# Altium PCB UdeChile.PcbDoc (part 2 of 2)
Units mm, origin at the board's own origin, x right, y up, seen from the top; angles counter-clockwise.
Board outline 201.93 x 30.26 mm, 2 copper layers (Top Layer, Bottom Layer); 212 components, 140 nets, 743 pads, 138 vias.
Unrouted connection lines stored in the file: 2.
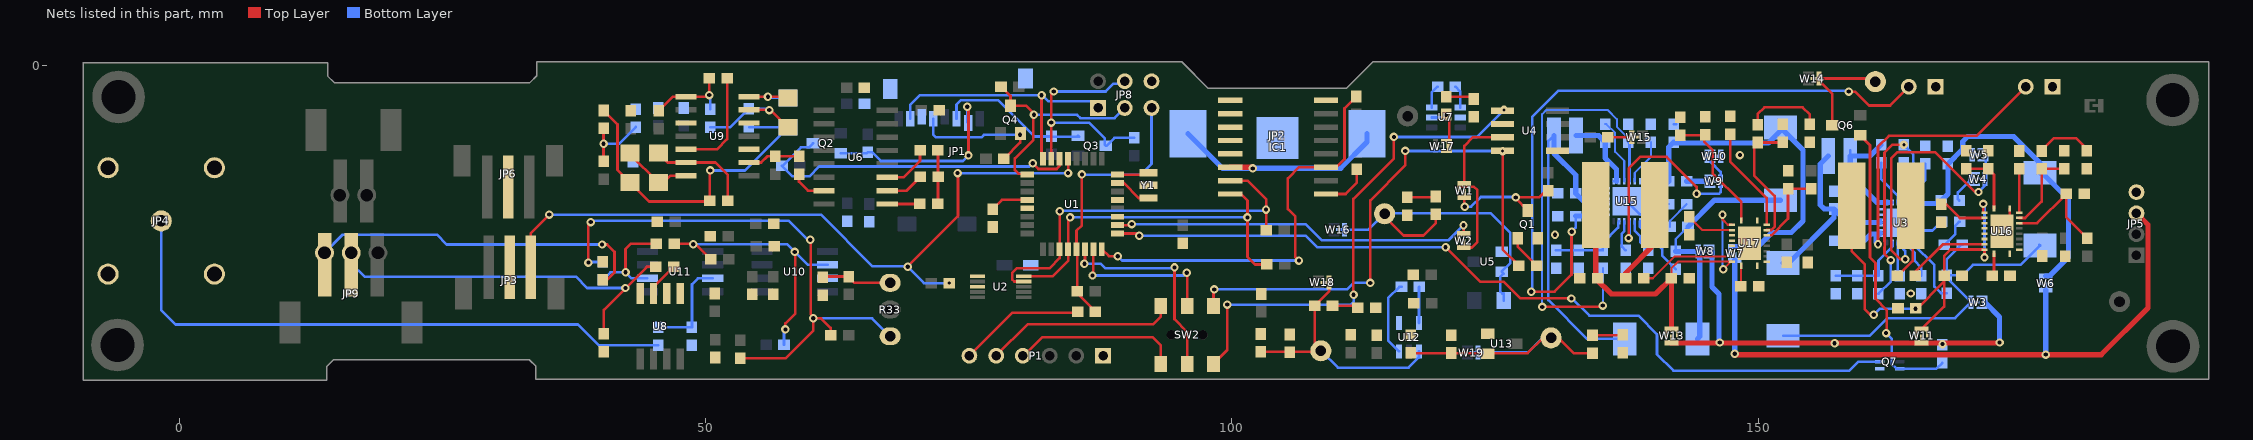
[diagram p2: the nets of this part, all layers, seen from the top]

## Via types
v1: diameter 0.8/0.8 (per signal layer), hole 0.4, Top Layer to Bottom Layer, tented both sides, 126 vias
v2: diameter 0.8/0.8 (per signal layer), hole 0.3, Top Layer to Bottom Layer, tented bottom, 6 vias
v3: diameter 0.8/0.8 (per signal layer), hole 0.3, Top Layer to Bottom Layer, tented top, 3 vias
v4: diameter 0.6/0.8 (per signal layer), hole 0.3, Top Layer to Bottom Layer, tented bottom, 2 vias
v5: diameter 0.8/0.8 (per signal layer), hole 0.4, Top Layer to Bottom Layer, tented bottom, 1 vias

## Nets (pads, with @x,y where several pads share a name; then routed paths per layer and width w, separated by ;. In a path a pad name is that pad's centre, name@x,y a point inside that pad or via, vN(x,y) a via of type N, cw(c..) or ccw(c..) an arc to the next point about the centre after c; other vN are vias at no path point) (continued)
CS: Q2.3 R71.1 U1.14 | length 32.1
  Top Layer w0.25: v1(81.073,-9.301) 81.606,-9.833 83.343,-9.833 83.633,-9.543 U1.14@83.633,-8.878
  Bottom Layer w0.25: Q2.3@60.204,-7.399 59.829,-7.774 59.063,-7.774 57.304,-9.534 R71.1@57.254,-9.534 58.249,-10.529 59.849,-10.529 60.776,-9.602 80.771,-9.602 v1(81.073,-9.301)
CS_L: JP1.2 Q2.2 R70.1 | length 19
  Top Layer w0.25: v1(74.855,-3.919) 74.967,-4.031 v1(74.967,-8.548)
  Bottom Layer w0.25: Q2.2@62.844,-8.349 65.292,-8.349 R70.1@65.402,-8.239 65.813,-8.239 66.649,-9.075 74.439,-9.075 v1(74.967,-8.548) ; v1(74.855,-3.919) 74.855,-5.397 JP1.2@74.929,-5.471
D: R12.2 SW2.4 U4.4 | length 51.4
  Top Layer w0.25: SW2.4@98.243,-22.855 98.243,-21.358 v1(98.325,-21.276) ; v1(113.142,-20.661) 113.142,-12.819 113.14,-12.818 116.458,-9.5 v1(116.458,-8.124) ; U4.4@125.712,-8.107 125.712,-17.484 R12.2@127.25,-19.022
  Bottom Layer w0.25: v1(98.325,-21.276) 110.919,-21.276 111.534,-20.661 v1(113.142,-20.661) ; v1(116.458,-8.124) v4@125.716,-8.124
  other v4: 125.716,-8.137
D0/RX: SW2.2 U1.30 | length 19.8
  Top Layer w0.25: v1@86.033,-18.793 U1.30@86.033,-17.463 ; v1(94.539,-19.186) 94.539,-24.112 95.743,-25.316 SW2.2@95.743,-28.355
  Bottom Layer w0.25: v1(85.981,-18.846) 87.547,-18.846 87.979,-19.277 94.449,-19.277 v1(94.539,-19.186)
D1/TX: SW2.5 U1.31 | length 14.8
  Top Layer w0.25: v1(86.753,-19.958) 86.833,-19.878 U1.31@86.833,-17.463 ; v1(95.697,-19.686) 95.743,-19.731 SW2.5@95.743,-22.855
  Bottom Layer w0.25: v1(86.753,-19.958) 95.425,-19.958 v1(95.697,-19.686)
ENA_S_M: Q6.1 Q7.3 R76.1 | length 28.4
  Top Layer w0.25: Q6.1@159.676,-6.65 160.61,-7.583 160.61,-18.247 161.133,-18.77 ; 161.135,-18.773 161.133,-18.77 ; v1@162.27,-25.627 162.193,-25.551 162.193,-23.214 161.133,-22.153 161.133,-18.77
  Bottom Layer w0.25: v1(162.147,-25.428) 162.67,-25.95 162.67,-28.349 163.13,-28.809 Q7.3@163.445,-28.809 166.924,-28.809 R76.1@167.485,-28.248
ENA_SENS: Q7.5 U1.1 | length 79.3
  Top Layer w0.25: U1.1@89.126,-15.971 90.977,-15.971 v1(91.192,-16.186) ; v1(120.297,-17.264) 123.599,-20.566 125.835,-20.566 127.389,-22.12 132.225,-22.12 v1(132.248,-22.143)
  Bottom Layer w0.25: v1(91.192,-16.186) 107.02,-16.186 108.099,-17.264 v1(120.297,-17.264) ; v1@132.26,-22.085 133.948,-23.772 138.602,-23.772 140.383,-25.553 140.383,-27.446 141.931,-28.994 158.655,-28.994 159.49,-28.159 Q7.5@161.545,-28.159
GND: C1.1 C2.1 C3.1 C6.2 C7.1 C8.1 C10.1 C11.1 C12.1 C13.1 C15.2 C16.2 C17.2 C18.2 C19.2 C22.2 C23.2 C24.2 C25.2 C26.2 C27.2 C28.1 C29.1 C30.1 C31.1 C32.1 C33.1 C34.1 C35.1 C36.2 C37.1 C38.1 C39.1 C40.1 C41.1 C43.2 C44.1 C45.1 C46.2 C48.1 C49.2 C50.2 C51.2 C52.2 C53.2 C54.2 C55.2 C56.2 C58.1 C59.2 C60.2 C61.2 C62.2 C63.2 C64.2 C65.2 D3.1 IC1.8 IC1.9 IC1.10 IC1.11 IC1.12 IC1.13 JP1.0 JP1.6 JP2.2 JP3.2 JP4.2 JP5.4 JP6.2 JP8.6 LED2.2 LED5.2 P1.1 P2.1 P3.1 Q1.2 Q7.4 R20.1 R23.1 R25.1 R34.1 R36.2 R37.1 R41.2 R45.2 R48.1 R49.1 R52.2 R53.2 R56.1 R57.1 R61.1 R62.1 R65.1 R67.1 U1.3 U1.5 U1.21 U2.1 U2.3 U3.6 U3.17 U3.18 U3.25 U4.5 U5.1 U7.5 U8.4 U9.3 U9.5 U9.10 U10.3 U12.4 U13.1 U15.6 U15.17 U15.18 U15.25 U16.11 U16.12 U16.20 U16.21 U17.11 U17.12 U17.20 U17.21 W5.1 W10.1 Y1.2 | length 7.8
  Top Layer w0.2: U16.21@173.145,-15.739 173.895,-14.989 U16.20@173.895,-13.589
  Top Layer w0.25: C65.2@149.898,-20.838 C65.2@150.048,-20.988
  Bottom Layer w0.2: C41.1@141.965,-5.587 C41.1@142.251,-5.587
  Bottom Layer w0.25: U15.25@137.52,-12.914 138.77,-14.164 U15.6@139.42,-14.164 ; U3.25@163.514,-14.926 164.764,-16.176 U3.6@165.414,-16.176
  other v1: 164.486,-21.668 130.69,-16.076 148.257,-8.52
I/O: JP3.1 R8.2 U1.13 | length 69.1
  Top Layer w0.25: JP3.1@33.381,-19.177 33.381,-15.943 v1(35.15,-14.174) ; v1(69.192,-19.131) 69.192,-19.099 73.977,-14.314 v1@73.977,-10.227 ; v1(84.433,-10.227) U1.13@84.433,-8.878
  Bottom Layer w0.25: v1(35.15,-14.174) 60.951,-14.174 65.857,-19.08 69.136,-19.08 69.187,-19.131 v1(69.192,-19.131) ; v1@69.228,-19.173 70.733,-20.677 v2(73.136,-20.677) ; v1(73.931,-10.227) v1(84.433,-10.227)
MISO: JP1.7 JP8.1 U1.16 | length 26.2
  Top Layer w0.25: v1(81.911,-2.824) 81.911,-8.756 U1.16@82.033,-8.878
  Bottom Layer w0.25: JP1.7@69.429,-5.071 69.429,-3.759 70.364,-2.824 81.975,-2.824 82.564,-3.414 86.655,-3.414 JP8.1@87.28,-4.039
MOSI: JP8.4 Q3.3 R73.1 U1.15 | length 25.8
  Top Layer w0.25: U1.15@82.833,-8.878 82.846,-8.865 v1@82.846,-2.703 ; v1@82.846,-5.435 v1@82.846,-2.703 ; v1(83.075,-2.473) v1@82.846,-2.703
  Bottom Layer w0.25: v1(82.832,-5.435) 86.441,-5.435 87.914,-6.908 87.914,-7.513 Q3.3@88.014,-7.613 88.114,-7.613 88.844,-6.884 R73.1@90.733,-6.884 ; v1(83.075,-2.473) 88.006,-2.474 88.742,-1.738 89.58,-1.738 JP8.4@89.82,-1.499
MOSI_L: JP1.3 Q3.2 R72.1 | length 14.7
  Bottom Layer w0.25: JP1.3@73.829,-5.071 73.829,-3.718 74.253,-3.294 77.791,-3.294 81.244,-6.747 R72.1@82.856,-6.747 82.87,-6.761 85.472,-6.761 Q3.2@85.374,-6.663
NetC1_2: C1.2 D7.2 L1.2 U3.15 U3.16 | length 19.1
  Bottom Layer w0.25: 161.614,-14.926 U3.16@161.614,-14.676
  Bottom Layer w0.5: D7.2@152.36,-18.769 152.896,-18.769 157.202,-14.463 C1.2@157.202,-13.636 ; L1.2@156.648,-8.601 155.886,-9.362 155.886,-13.246 156.276,-13.636 C1.2@157.202,-13.636 ; 161.614,-14.926 158.492,-14.926 C1.2@157.202,-13.636
NetC3_2: C3.2 U1.20 | length 3.6
  Top Layer w0.25: C3.2@77.261,-13.651 78.141,-12.771 U1.20@80.541,-12.771
NetC4_1: C4.1 U3.21 | length 4.5
  Bottom Layer w0.25: C4.1@161.671,-9.232 161.671,-10.795 163.264,-12.388 U3.21@163.264,-13.026
NetC4_2: C4.2 L1.1 U3.19 U3.20 | length 10.9
  Bottom Layer w0.25: L1.1@158.748,-8.601 L1.1@158.748,-8.057 ; 162.514,-13.026 U3.20@162.764,-13.026
  Bottom Layer w0.5: C4.2@161.671,-7.532 160.602,-8.601 L1.1@158.748,-8.601 158.748,-10.505 161.269,-13.026 U3.19@162.264,-13.026 162.514,-13.026
NetC5_1: C5.1 pad.1@114.501,-14.09 R13.2 U5.2 W16.1 | length 31.9
  Top Layer w0.25: pad.1@114.501,-14.09 114.501,-14.351 116.304,-16.154 118.178,-16.154 119.378,-14.954 R13.2@119.378,-14.155
  Bottom Layer w0.25: W16.1@110.399,-15.603 W16.1@110.699,-15.603 112.988,-15.603 pad.1@114.501,-14.09 pad.1@114.456,-14.045 ; C5.1@125.811,-22.344 125.811,-21.669 125.688,-21.669 125.483,-21.464 125.483,-20.109 125.811,-19.78 U5.2@125.63,-19.599 126.455,-18.774 126.455,-15.94 124.555,-14.04 122.382,-14.04 122.377,-14.045 pad.1@114.456,-14.045 ; pad.1@114.456,-14.045 114.453,-14.045 114.448,-14.04 114.453,-14.042 pad.1@114.456,-14.045
NetC9_1: C9.1 U6.9 | length 3.1
  Top Layer w0.25: U6.9@67.252,-13.16 C9.1@70.349,-13.16
NetC9_2: C9.2 R15.2 R19.2 | length 5.1
  Top Layer w0.25: C9.2@72.069,-13.14 R15.2@72.069,-8.058
NetC14_1: C14.1 U7.4 | length 2.2
  Bottom Layer w0.25: C14.1@121.233,-2.013 121.679,-2.46 U7.4@121.679,-3.993
NetC14_2: C14.2 U7.3 | length 2.2
  Bottom Layer w0.25: U7.3@118.979,-3.993 118.979,-2.566 C14.2@119.533,-2.013
NetC16_1: C16.1 R24.1 U11.3 | length 9.5
  Bottom Layer w0.25: R24.1@45.483,-24.885 C16.1@48.701,-24.885 48.701,-20.801 49.279,-20.222 U11.3@50.675,-20.222
NetC20_1: C20.1 U12.3 | length 7.2
  Bottom Layer w0.25: U12.3@115.876,-27.17 114.84,-26.134 114.84,-22.112 115.911,-21.04 C20.1@116.104,-21.04
NetC20_2: C20.2 U12.5 | length 3.4
  Bottom Layer w0.25: U12.5@117.776,-24.47 117.776,-21.069 C20.2@117.804,-21.04
NetC21_1: C21.1 R27.2 R33.1 R68.1 | length 54.5
  Top Layer w0.25: v1(38.863,-18.729) 38.863,-15.1 v1(39.082,-14.882) ; C21.1@53.295,-27.82 57.61,-27.82 60.227,-25.202 v1(60.227,-24.023) ; v1(59.944,-16.56) 59.97,-16.586 59.97,-23.595 60.227,-23.852 v1(60.227,-24.023) ; R68.1@61.882,-25.629 61.882,-24.95 60.955,-24.023 v1(60.227,-24.023)
  Bottom Layer w0.25: v1(38.863,-18.729) 38.922,-18.67 R27.2@40.228,-18.67 ; v1(39.082,-14.882) 39.218,-14.746 57.856,-14.746 59.67,-16.56 v1(59.944,-16.56) ; v1(60.227,-24.023) 65.809,-24.023 67.523,-25.738 R33.1@67.528,-25.733
NetC26_1: C26.1 R31.1 R32.2 | length 6.9
  Top Layer w0.25: R32.2@40.301,-9.111 R31.1@40.301,-5.98
  Bottom Layer w0.25: v1(40.302,-7.448) 41.772,-7.448 C26.1@43.366,-5.854
NetC30_2: C30.2 C31.2 LED4.2 pad.1@108.451,-27.11 U12.1 W18.1 | length 23.4
  Top Layer w0.25: C30.2@102.755,-27.217 108.344,-27.217 pad.1@108.451,-27.11 ; pad.1@107.852,-26.511 LED4.2@107.852,-22.838 109.228,-21.462 W18.1@109.228,-20.619 W18.1@108.928,-20.619
  Bottom Layer w0.25: pad.1@108.451,-27.11 110.052,-28.711 116.781,-28.711 117.776,-27.716 U12.1@117.776,-27.17
NetC34_2: C34.2 C35.2 pad.1@130.316,-25.882 R39.2 U13.2 W19.1 | length 26.3
  Top Layer w0.25: C35.2@116.973,-27.315 116.998,-27.34 128.079,-27.34 129.537,-25.882 pad.1@130.316,-25.882 131.002,-25.882 132.46,-27.34 R39.2@134.252,-27.34
  Bottom Layer w0.25: W19.1@123.085,-27.275 W19.1@123.385,-27.275 128.122,-27.275 129.515,-25.882 pad.1@130.316,-25.882
NetC37_2: C37.2 U3.23 | length 4.3
  Bottom Layer w0.25: U3.23@164.264,-13.026 164.264,-12.52 165.862,-10.922 C37.2@165.862,-9.359
NetC38_2: C38.2 P2.2 U3.13 U3.14 | length 29.8
  Top Layer w0.25: v1(161.379,-16.99) 161.379,-7.715 162.401,-6.693 170.743,-6.693 P2.2@175.413,-2.022
  Bottom Layer w0.5: C38.2@158.965,-16.637 160.096,-16.637 160.725,-16.008 161.532,-16.008 ; v1(161.379,-16.99) 161.183,-16.795 161.183,-16.356 161.532,-16.008 ; 161.614,-15.926 161.532,-16.008
NetC39_2: C39.2 D6.2 R9.1 U3.1 U3.24 W6.2 | length 29.8
  Bottom Layer w0.25: U3.24@164.764,-13.026 U3.24@164.769,-13.021
  Bottom Layer w0.5: 165.454,-13.113 R9.1@167.12,-13.113 ; R9.1@167.402,-12.831 168.021,-12.212 C39.2@168.021,-9.359 169.424,-7.956 169.424,-7.228 169.901,-6.751 174.262,-6.751 176.774,-9.264 D6.2@176.774,-10.201 176.959,-10.201 179.475,-12.716 179.475,-18.204 177.678,-20.001 W6.2@177.318,-20.001
NetC40_2: C40.2 D9.2 L2.2 U15.15 U15.16 | length 34.3
  Bottom Layer w0.25: L2.2@130.592,-6.656 130.064,-7.184 130.064,-22.289 133.753,-25.978 D9.2@137.331,-25.978
  Bottom Layer w0.5: L2.2@130.592,-6.656 130.592,-8.357 132.655,-10.42 C40.2@132.655,-12.152 133.419,-12.916 135.602,-12.916
NetC41_2: C41.2 D8.2 R50.1 U15.1 U15.24 W7.2 | length 34.2
  Bottom Layer w0.25: R50.1@141.423,-11.083 R50.1@141.423,-11.009
  Bottom Layer w0.5: 139.399,-11.083 R50.1@141.423,-11.083 ; R50.1@141.496,-11.009 141.496,-7.756 C41.2@141.965,-7.287 ; C41.2@141.965,-7.368 150.956,-7.368 152.116,-6.208 D8.2@152.116,-5.896 154.245,-8.025 154.245,-14.763 153.139,-15.869 151.312,-15.869 149.98,-17.201 W7.2@147.769,-17.201
NetC42_1: C42.1 U15.21 | length 6.3
  Bottom Layer w0.2: C42.1@135.453,-5.57 135.569,-5.57 136.398,-6.4 136.398,-8.197 137.27,-9.069 U15.21@137.27,-11.014
NetC42_2: C42.2 L2.1 U15.19 U15.20 | length 7.2
  Bottom Layer w0.2: U15.19@136.27,-11.014 U15.19@136.27,-10.991
  Bottom Layer w0.5: L2.1@132.692,-6.656 134.838,-6.656 C42.2@135.453,-7.27 135.453,-8.786 136.523,-9.857 136.523,-10.991
NetC44_2: C44.2 U15.23 | length 4.4
  Bottom Layer w0.2: U15.23@138.27,-11.014 138.27,-10.201 139.806,-8.665 C44.2@139.806,-7.287
NetC45_2: C45.2 P3.2 U15.13 U15.14 | length 68.1
  Top Layer w0.25: v1(128.43,-21.495) 130.642,-21.495 132.259,-19.878 132.259,-15.806 v1(132.273,-15.792) ; v1(158.6,-2.487) 159.207,-2.487 160.529,-3.809 162.522,-3.809 P3.2@164.309,-2.022
  Bottom Layer w0.25: v1(128.43,-21.495) 128.526,-21.399 128.526,-4.908 131.042,-2.392 158.506,-2.392 v1(158.6,-2.487) ; v1(132.273,-15.792) 132.655,-15.41 C45.2@132.655,-14.311
  Bottom Layer w0.5: C45.2@132.655,-14.311 135.174,-14.311 135.557,-13.927
NetC46_1: C46.1 C48.2 L3.1 U16.2 U16.9 W11.2 | length 38.4
  Top Layer w0.25: L3.1@158.876,-13.331 158.876,-17.639 160.132,-18.895 160.132,-23.167 160.656,-23.69 v1(160.963,-23.69) ; v1(164.929,-23.113) 164.929,-23.265 167.653,-20.541 ; W11.2@165.513,-25.044 167.656,-22.901 167.653,-22.901 167.653,-20.541 ; v1(171.367,-13.151) 171.367,-13.86 U16.2@171.495,-13.989 ; v1@171.495,-18.235 U16.9@171.495,-17.489 168.245,-17.489 167.653,-18.081 C48.2@167.653,-19.963 167.653,-20.541
  Bottom Layer w0.25: v1(160.963,-23.69) 161.554,-23.099 164.764,-23.099 164.929,-23.265 v1(164.929,-23.113) ; v1(171.494,-18.235) v1@171.494,-13.279
NetC47_1: C47.1 L3.2 R58.2 U16.4 U16.5 U16.6 U16.7 | length 9.3
  Top Layer w0.25: C47.1@163.197,-19.96 163.296,-19.96 164.668,-18.588 164.668,-13.522 L3.2@164.476,-13.331 L3.2@163.332,-14.475 ; L3.2@165.312,-14.864 L3.2@165.474,-15.026 ; R58.2@167.348,-15.026 R58.2@167.385,-14.989
NetC47_2: C47.2 U16.8 | length 8
  Top Layer w0.25: C47.2@164.897,-19.96 164.897,-19.619 167.527,-16.989 U16.8@171.495,-16.989
NetC49_1: C49.1 C50.1 U16.1 | length 6.1
  Top Layer w0.25: C49.1@169.747,-9.809 C50.1@171.841,-9.809 172.395,-10.364 U16.1@172.395,-13.589
NetC51_1: C51.1 R60.2 U16.18 | length 8
  Top Layer w0.25: U16.18@174.795,-14.489 175.364,-14.489 176.916,-12.936 176.916,-9.809 C51.1@179.064,-9.809
NetC54_1: C54.1 R60.1 | length 5.4
  Top Layer w0.25: R60.1@176.911,-8.105 178.106,-6.91 180.203,-6.91 181.219,-7.926 C54.1@181.219,-8.066
NetC55_1: C55.1 U16.10 | length 2.1
  Top Layer w0.25: C55.1@172.395,-20.015 U16.10@172.395,-17.889
NetC56_1: C56.1 C58.2 L4.1 U17.2 U17.9 W13.2 | length 35.4
  Top Layer w0.2: L4.1@134.554,-13.256 L4.1@134.734,-13.436 ; C58.2@141.749,-19.92 141.749,-19.27 142.38,-18.639 U17.9@147.393,-18.639 ; v1(146.605,-14.194) 146.605,-14.64 147.103,-15.139 U17.2@147.498,-15.139 ; v1(146.668,-19.363) U17.9@147.393,-18.639 ; U17.9@147.498,-18.639 U17.9@147.393,-18.639
  Top Layer w0.5: L4.1@134.734,-13.436 134.554,-13.616 134.554,-20.237 136.04,-21.724 140.246,-21.724 C58.2@141.749,-20.221 141.749,-19.92 141.764,-19.935 W13.2@141.764,-25.039
  Bottom Layer w0.2: v1(146.605,-14.194) 146.605,-19.299 v1(146.668,-19.363)
NetC57_1: C57.1 L4.2 R63.2 U17.4 U17.5 U17.6 U17.7 | length 8.1
  Top Layer w0.2: L4.2@140.154,-16.969 L4.2@140.154,-13.256
  Top Layer w0.5: C57.1@137.409,-20.218 137.409,-19.714 L4.2@140.154,-16.969
NetC57_2: C57.2 U17.8 | length 9.2
  Top Layer w0.2: C57.2@139.109,-20.218 139.991,-20.218 142.07,-18.139 U17.8@147.498,-18.139
NetC59_1: C59.1 C60.1 U17.1 | length 11.9
  Top Layer w0.25: C59.1@142.586,-6.638 144.878,-6.638 144.878,-7.267 145.666,-8.055 145.666,-10.254 148.398,-12.987 U17.1@148.398,-14.739
NetC61_1: C61.1 R64.2 U17.18 | length 12.2
  Top Layer w0.25: U17.18@150.798,-15.639 151.246,-15.639 151.554,-15.331 151.554,-12.385 149.606,-10.437 149.606,-7.658 R64.2@149.941,-7.323 152.318,-7.323 C61.1@152.334,-7.307
NetC64_1: C64.1 R64.1 | length 7.4
  Top Layer w0.25: R64.1@149.941,-5.623 149.941,-4.632 150.592,-3.981 154.221,-3.981 154.903,-4.663 C64.1@154.903,-5.606
NetC65_1: C65.1 U17.10 | length 2
  Top Layer w0.2: C65.1@148.348,-20.988 148.348,-19.089 U17.10@148.398,-19.039
NetD1_1: D1.1 R22.2 R30.1 U9.6 | length 10.8
  Top Layer w0.25: U9.6@54.118,-4.217 56.162,-4.217 D1.1@57.824,-5.879
  Bottom Layer w0.25: R30.1@50.432,-5.871 52.341,-5.871 R22.2@54.09,-4.122 55.919,-4.122 v1(56.042,-4.245)
NetD1_2: D1.2 D2.1 U9.7 | length 5.6
  Top Layer w0.25: U9.7@54.118,-2.967 v1(55.915,-2.967) D1.2@57.712,-2.967
  Bottom Layer w0.25: v1(55.915,-2.967) 56.027,-3.079 D2.1@57.824,-3.079
NetD2_2: D2.2 D5.2 R22.1 R31.2 R35.1 | length 31.9
  Top Layer w0.25: R31.2@40.301,-4.28 41.62,-5.6 41.62,-9.927 D5.2@42.824,-11.131 44.624,-12.931 50.305,-12.931 R35.1@50.395,-12.841 50.395,-10.022 v1(50.439,-9.977)
  Bottom Layer w0.25: v1(50.439,-9.977) 53.726,-9.977 D2.2@57.824,-5.879 R22.1@54.147,-5.879
NetD4_1: D4.1 R35.2 U9.13 | length 9.9
  Top Layer w0.25: D4.1@45.512,-8.331 46.398,-9.217 U9.13@48.118,-9.217 50.932,-9.217 52.095,-10.38 R35.2@52.095,-12.841
NetD4_2: D4.2 D5.1 U9.14 | length 6.8
  Top Layer w0.25: D5.1@42.824,-8.331 42.824,-8.442 D4.2@45.512,-11.131 45.993,-11.131 46.657,-10.467 U9.14@48.118,-10.467
NetIC1_1: IC1.1 R2.2 | length 4.6
  Top Layer w0.25: IC1.1@108.946,-12.21 110.797,-12.21 111.853,-11.153 R2.2@111.853,-9.877
NetIC1_14: IC1.14 JP2.1 | length 22.4
  Top Layer w0.5: IC1.14@99.846,-9.67 101.859,-9.67 v1(101.973,-9.784)
  Bottom Layer w0.5: JP2.1@95.823,-6.485 99.102,-9.765 110.33,-9.765 112.823,-7.272 JP2.1@112.823,-6.485
NetLED1_2: LED1.2 R46.1 | length 2.8
  Bottom Layer w0.25: LED1.2@167.679,-17.018 167.729,-17.018 168.7,-16.047 168.7,-15.234 169.075,-14.859 R46.1@169.125,-14.859
NetLED2_1: LED2.1 R13.1 | length 2.6
  Top Layer w0.25: LED2.1@116.674,-12.515 R13.1@119.318,-12.515
NetLED3_1: LED3.1 R20.2 | length 2.7
  Top Layer w0.25: LED3.1@120.365,-2.965 122.737,-2.965 R20.2@122.962,-3.19
NetLED3_2: LED3.2 U7.2 W17.2 | length 4.6
  Top Layer w0.25: LED3.2@120.365,-4.688 LED3.2@120.356,-4.697 ; W17.2@120.646,-7.658 120.646,-4.987 LED3.2@120.356,-4.697 ; LED3.2@120.356,-4.697 120.344,-4.685 v5(120.344,-4.709) LED3.2@120.356,-4.697
  Bottom Layer w0.25: U7.2@118.979,-4.943 120.11,-4.943 v5(120.344,-4.709)
NetLED4_1: LED4.1 R37.2 | length 2.2
  Top Layer w0.25: LED4.1@109.552,-22.838 R37.2@111.793,-22.838
NetLED5_1: LED5.1 R39.1 | length 2.8
  Top Layer w0.25: R39.1@134.252,-25.64 LED5.1@137.1,-25.64
NetLED6_2: LED6.2 R54.1 | length 2.8
  Bottom Layer w0.2: LED6.2@141.623,-15.327 141.623,-14.741 R54.1@143.196,-13.168
NetQ1_1: Q1.1 R12.1 | length 3.3
  Top Layer w0.25: Q1.1@127.15,-16.425 127.15,-17.222 R12.1@128.95,-19.022
NetQ1_3: Q1.3 R11.1 W1.1 | length 11.6
  Top Layer w0.25: W1.1@122.082,-12.236 W1.1@122.082,-12.536 122.082,-13.384 v1(122.118,-13.42) ; Q1.3@128.1,-13.785 126.963,-12.648 v1(126.963,-12.537) 129.192,-12.537 R11.1@130.084,-11.645
  Bottom Layer w0.25: v1(122.118,-13.42) 122.729,-13.42 123.646,-12.502 126.928,-12.502 v1(126.963,-12.537)
NetQ6_3: pad.1@161.131,-1.538 Q6.3 W14.1 | length 10.8
  Top Layer w0.25: W14.1@155.481,-1.244 W14.1@155.564,-1.244 ; Q6.3@157.036,-5.7 157.036,-2.717 W14.1@155.564,-1.244 ; pad.1@161.131,-1.538 160.837,-1.244 W14.1@155.781,-1.244 W14.1@155.564,-1.244
NetR9_2: R9.2 W4.2 | length 2.8
  Bottom Layer w0.25: R9.2@169.102,-12.831 168.966,-12.695 168.966,-12.071 W4.2@170.242,-10.795 170.242,-10.797 W4.2@170.117,-10.922
NetR10_1: R10.1 W15.1 | length 2.6
  Top Layer w0.25: R10.1@135.721,-6.812 W15.1@137.974,-6.812 W15.1@138.274,-6.812
NetR14_2: R14.2 R18.1 U9.2 | length 5
  Top Layer w0.25: U9.2@54.118,-9.217 55.265,-9.217 55.855,-8.628 R14.2@56.608,-8.628 56.622,-8.642 R18.1@58.873,-8.642
NetR15_1: R15.1 U6.11 | length 4.8
  Top Layer w0.25: U6.11@67.252,-10.62 68.824,-10.62 70.369,-9.076 R15.1@70.369,-8.058
NetR16_1: R16.1 R26.2 R28.2 U10.2 | length 26.9
  Top Layer w0.25: R26.2@47.002,-16.926 v1@48.818,-16.926 ; v1(48.818,-16.997) 49.07,-16.997 R28.2@50.483,-18.409 ; v1(57.579,-25.078) 57.579,-24.515 58.514,-23.58 58.514,-17.755 v1(58.472,-17.713)
  Bottom Layer w0.25: v1(48.818,-16.997) 57.756,-16.997 v1(58.472,-17.713) ; R16.1@57.441,-26.524 57.441,-25.216 v1(57.579,-25.078) ; v1@58.483,-17.702 59.733,-18.952 U10.2@61.577,-18.952
NetR17_2: R17.2 U8.1 U8.2
NetR18_2: R18.2 U6.7 | length 3.4
  Top Layer w0.25: R18.2@58.873,-10.342 58.873,-11.035 59.728,-11.89 U6.7@61.252,-11.89
NetR19_1: R19.1 U6.10 | length 3.7
  Top Layer w0.25: U6.10@67.252,-11.89 69.105,-11.89 70.388,-10.608 R19.1@70.388,-10.562
NetR21_1: R21.1 U8.3 | length 3.3
  Top Layer w0.25: U8.3@45.051,-21.655 45.051,-21.039 R21.1@46.959,-19.131
NetR26_1: R26.1 R27.1 U11.6 | length 10.1
  Top Layer w0.25: v1(42.391,-19.656) 42.391,-17.462 42.927,-16.926 R26.1@45.302,-16.926
  Bottom Layer w0.25: R27.1@40.228,-20.37 40.941,-19.656 v1(42.391,-19.656) 42.956,-20.222 U11.6@44.456,-20.222
NetR29_1: R29.1 R30.2 R38.2 U9.8 | length 8.4
  Top Layer w0.25: R29.1@45.547,-4.296 46.876,-2.967 U9.8@48.118,-2.967 50.199,-2.967 v1(50.352,-2.814) R38.2@50.352,-1.22
  Bottom Layer w0.25: v1(50.352,-2.814) 50.432,-2.894 R30.2@50.432,-4.171
NetR33_3: R33.3 R34.2 R69.2 | length 6.7
  Top Layer w0.25: R34.2@61.135,-20.135 61.213,-20.057 R69.2@63.591,-20.057 63.591,-20.107 64.137,-20.653 R33.3@67.528,-20.653
NetR38_1: R38.1 U9.12 | length 10.1
  Top Layer w0.25: U9.12@48.118,-7.967 51.091,-7.967 52.052,-7.006 R38.1@52.052,-1.22
NetR40_2: R40.2 U3.7 | length 6.4
  Bottom Layer w0.25: U3.7@164.764,-16.826 164.764,-16.996 166.726,-18.958 166.726,-21.018 167.347,-21.639 R40.2@167.894,-21.639
NetR41_1: R41.1 U3.10 | length 3.2
  Bottom Layer w0.25: U3.10@163.264,-16.826 163.264,-19.793 R41.1@163.449,-19.978
NetR45_1: R45.1 U3.8 | length 3.7
  Bottom Layer w0.25: U3.8@164.264,-16.826 164.264,-17.198 164.846,-17.78 164.846,-18.542 165.481,-19.177 R45.1@165.481,-19.978
NetR46_2: R46.2 U3.5 | length 2.3
  Bottom Layer w0.25: U3.5@165.414,-15.676 166.558,-15.676 167.375,-14.859 R46.2@167.425,-14.859
NetR47_1: R47.1 R48.2 R49.2 U3.11 | length 7.8
  Bottom Layer w0.25: R49.2@157.353,-19.978 R48.2@159.385,-19.978 R47.1@161.417,-19.978 161.417,-18.542 162.764,-17.195 U3.11@162.764,-16.826
NetR50_2: R50.2 W9.2 | length 1.9
  Bottom Layer w0.5: R50.2@143.196,-11.009 W9.2@145.116,-11.009
NetR51_2: R51.2 U15.7 | length 5.9
  Bottom Layer w0.25: U15.7@138.77,-14.814 138.77,-15.333 140.876,-17.439 140.876,-18.07 R51.2@142.159,-19.353
NetR52_1: R52.1 U15.10 | length 3
  Bottom Layer w0.25: U15.10@137.27,-14.814 137.27,-15.74 137.035,-15.976 137.035,-17.208 R52.1@137.393,-17.567
NetR53_1: R53.1 U15.8 | length 3.3
  Bottom Layer w0.25: U15.8@138.27,-14.814 138.27,-15.711 138.777,-16.217 138.777,-16.791 R53.1@139.552,-17.567
NetR54_2: R54.2 U15.5 | length 2.3
  Bottom Layer w0.2: U15.5@139.42,-13.664 140.276,-13.664 140.772,-13.168 R54.2@141.496,-13.168
NetR55_1: R55.1 R56.2 R57.2 U15.11 | length 7.8
  Bottom Layer w0.25: R57.2@130.789,-17.569 R56.2@132.955,-17.569 135.232,-17.569 R55.1@135.234,-17.567 135.234,-16.852 136.685,-15.402 136.685,-14.9 U15.11@136.77,-14.814
NetR58_1: R58.1 U16.3 | length 4.7
  Top Layer w0.25: R58.1@167.376,-13.2 167.87,-13.2 169.159,-14.489 U16.3@171.495,-14.489
NetR59_1: R59.1 R62.2 U16.17 | length 10.7
  Top Layer w0.25: U16.17@174.795,-14.989 176.496,-14.989 R62.2@179.276,-12.208 179.276,-14.427 R59.1@181.272,-16.422
NetR61_2: R61.2 U16.19 | length 4.2
  Top Layer w0.25: U16.19@174.795,-13.989 R61.2@174.795,-9.813
NetR63_1: R63.1 U17.3 | length 4.6
  Top Layer w0.2: R63.1@143.442,-14.395 144.685,-15.639 U17.3@147.498,-15.639
NetR65_2: R65.2 U17.19 | length 10
  Top Layer w0.25: R65.2@147.356,-6.522 147.356,-9.154 150.798,-12.596 U17.19@150.798,-15.139
NetR66_1: R66.1 R67.2 U17.17 | length 7.7
  Top Layer w0.25: U17.17@150.798,-16.139 151.241,-16.139 152.83,-14.55 R67.2@152.83,-11.723 R66.1@155.022,-11.723
NetU1_7: U1.7 Y1.3 | length 3.5
  Top Layer w0.25: U1.7@89.126,-11.17 89.723,-11.17 91.141,-12.588 Y1.3@92.067,-12.588
NetU1_8: U1.8 Y1.1 | length 3
  Top Layer w0.25: U1.8@89.126,-10.371 91.884,-10.371 Y1.1@92.067,-10.188
NetU3_9: U3.9 W4.1 W5.2 | length 26
  Top Layer w0.25: v1(163.957,-18.415) 163.505,-18.415 162.624,-17.534 162.624,-8.821 163.191,-8.254 166.823,-8.254 170.596,-12.026 v1(170.927,-12.026)
  Bottom Layer w0.25: U3.9@163.764,-16.826 163.764,-17.438 163.957,-17.631 v1(163.957,-18.415) ; v1(170.927,-12.026) 171.542,-11.411 W4.1@171.542,-10.795 171.592,-10.795 171.617,-10.77 171.617,-8.498 W5.2@171.623,-8.492
NetU15_9: U15.9 W9.1 W10.2 | length 22.6
  Top Layer w0.25: v1(137.686,-16.4) 137.686,-9.775 138.782,-8.679 141.295,-8.679 144.145,-11.529 v1(144.145,-12.192)
  Bottom Layer w0.25: v1(137.686,-16.4) 137.77,-16.315 U15.9@137.77,-14.814 ; v1(144.145,-12.192) 146.262,-12.192 146.42,-12.033 W9.1@146.42,-11.005 146.42,-10.124 W10.2@145.446,-9.15
PD2: IC1.3 R6.2 U1.32 | length 40
  Top Layer w0.25: U1.32@87.633,-17.463 88.296,-18.126 v1(89.146,-18.126) ; v1(106.365,-18.543) 106.021,-18.199 106.021,-14.347 105.313,-13.639 105.313,-10.74 106.383,-9.67 IC1.3@108.946,-9.67 109.923,-9.67 110.694,-8.899 110.694,-4.085 R6.2@111.825,-2.954
  Bottom Layer w0.25: v1(89.146,-18.126) 89.554,-18.534 106.355,-18.534 v1(106.365,-18.543)
PD4: U1.2 W2.2 | length 35
  Top Layer w0.25: U1.2@89.126,-15.17 90.379,-15.17 v1(90.475,-15.074) ; v1(121.994,-15.178) 122.022,-15.205 W2.2@122.022,-15.999
  Bottom Layer w0.25: v1(90.475,-15.074) 107,-15.074 108.55,-16.624 120.548,-16.624 v1(121.994,-15.178)
PH_IN: JP4.1 R24.2 | length 57.1
  Bottom Layer w0.25: JP4.1@-1.718,-14.772 -1.718,-23.259 -0.366,-24.61 37.871,-24.61 39.846,-26.585 R24.2@45.483,-26.585
R: SW2.3 U4.1 | length 47.1
  Top Layer w0.25: SW2.3@98.243,-28.355 99.554,-27.044 v1(99.554,-22.721) ; v1(111.56,-21.786) 111.54,-21.765 111.54,-12.668 115.388,-8.82 v1(115.388,-6.795)
  Bottom Layer w0.25: v1(99.554,-22.721) 111.299,-22.721 111.568,-22.452 111.56,-22.443 v1(111.56,-21.786) ; v1(115.388,-6.795) 123.271,-6.795 v4(125.845,-4.221)
RST: C66.1 JP8.5 R1.1 U1.29 | length 26.4
  Top Layer w0.25: v1(85.746,-10.358) 85.746,-15.188 85.233,-15.701 U1.29@85.233,-17.463 85.306,-17.536 R1.1@85.306,-21.448 85.306,-21.663 C66.1@87.031,-23.388
  Bottom Layer w0.25: v1@85.714,-10.374 91.348,-10.374 92.36,-9.363 JP8.5@92.36,-4.039
RST_: C66.2 P1.6 | length 12
  Top Layer w0.25: P1.6@75.058,-27.577 79.155,-23.48 85.239,-23.48 C66.2@85.331,-23.388
RX_FTDI: P1.5 SW2.6 | length 18.2
  Top Layer w0.25: P1.5@77.598,-27.577 80.602,-24.573 92.535,-24.573 93.243,-23.866 SW2.6@93.243,-22.855
SCK: JP8.3 Q4.3 R75.1 U1.17 | length 21.3
  Top Layer w0.25: R75.1@78.059,-2.028 78.109,-2.028 78.962,-2.881 Q4.3@78.962,-3.827 80.449,-3.827 81.136,-4.514 81.136,-7.071 79.367,-8.84 79.367,-9.942 79.703,-10.279 80.449,-10.279 U1.17@80.541,-10.371
  Bottom Layer w0.25: v1(81.187,-4.692) 85.273,-4.692 85.595,-5.014 88.845,-5.014 JP8.3@89.82,-4.039
SCK_L: JP1.5 Q4.2 R74.1 | length 12.8
  Top Layer w0.25: R74.1@78.382,-8.847 78.374,-8.84 79.875,-7.34 v1(79.875,-6.593)
  Bottom Layer w0.25: JP1.5@71.629,-5.071 71.629,-6.599 71.862,-6.832 76.21,-6.832 76.448,-6.593 v1(79.875,-6.593)
SCL: IC1.16 R5.1 U1.28 U2.10 | length 35.2
  Top Layer w0.25: U2.10@80.226,-20.032 82.964,-20.032 84.433,-18.562 U1.28@84.433,-17.463 84.433,-14.622 v1(84.619,-14.437) ; IC1.16@99.846,-12.21 100.858,-12.21 101.48,-12.832 101.48,-18.199 102.187,-18.906 R5.1@103.303,-18.906
  Bottom Layer w0.25: v1(84.619,-14.437) v1(101.47,-14.437)
SDA: IC1.15 R4.1 U1.27 U2.9 | length 38.1
  Top Layer w0.25: U2.9@80.226,-20.532 79.319,-20.532 79.118,-20.331 79.118,-19.703 79.565,-19.256 82.695,-19.256 83.633,-18.317 U1.27@83.633,-17.463 v1(83.633,-13.844) ; IC1.15@99.846,-10.94 101.483,-10.94 103.252,-12.709 R4.1@103.252,-15.652
  Bottom Layer w0.25: v1(83.633,-13.844) 83.666,-13.812 103.116,-13.812 v1(103.234,-13.694)
T_GND: JP9.3 pad.3@13.79,-17.804 R25.2 | length 32.3
  Top Layer w0.25: v1(40.166,-17.012) 40.649,-17.012 41.339,-17.702 41.339,-19.667 40.641,-20.365 R25.2@40.205,-20.365
  Bottom Layer w0.25: pad.3@13.79,-17.804 15.524,-16.069 24.457,-16.069 25.4,-17.012 v1(40.166,-17.012)
T_S: JP9.2 pad.2@16.33,-17.804 R21.2 R23.2 | length 36.9
  Top Layer w0.25: R23.2@40.333,-25.471 40.333,-23.214 44.417,-19.131 R21.2@45.26,-19.131
  Bottom Layer w0.25: pad.2@16.33,-17.804 16.33,-18.8 17.6,-20.07 37.667,-20.07 38.742,-21.145 v1(42.376,-21.145)
TX_EN: U4.2 U4.3 W1.2 W2.1 | length 16.2
  Top Layer w0.25: W1.2@121.557,-11.536 121.557,-11.511 122.96,-11.511 123.307,-11.857 123.307,-16.787 122.795,-17.299 W2.1@122.022,-17.299 W2.1@122.022,-16.999 ; W1.2@122.082,-11.236 122.082,-7.631 122.876,-6.837 U4.3@125.712,-6.837
TX_FTDI: P1.4 SW2.1 | length 15.9
  Top Layer w0.25: P1.4@80.138,-27.577 80.255,-27.577 82.011,-25.821 92.452,-25.821 93.243,-26.612 SW2.1@93.243,-28.355
VCC: JP5.3 W6.1 W7.1 | length 65.9
  Top Layer w0.5: v1(147.769,-27.383) 147.679,-27.473 v1(177.308,-27.473) 182.585,-27.473 187.028,-23.03 187.028,-15.134 JP5.3@185.928,-14.034
  Bottom Layer w0.5: v1(147.769,-27.383) W7.1@147.769,-18.501 ; v1@177.318,-27.573 W6.1@177.318,-21.338
VREGN1: C36.1 R47.2 U3.22 | length 22.6
  Top Layer w0.25: v1(162.588,-18.493) 161.994,-17.899 161.994,-17.259 162.004,-17.249 162.004,-16.731 161.994,-16.721 161.994,-8.283 162.745,-7.532 v3(163.83,-7.532)
  Bottom Layer w0.25: R47.2@161.417,-21.678 162.588,-20.507 v1(162.588,-18.493) ; U3.22@163.764,-13.026 163.764,-11.877 164.719,-10.922 164.719,-8.421 164.075,-7.777 164.025,-7.777 163.83,-7.582 v3(163.83,-7.532)
VREGN2: C43.1 R55.2 U15.22 | length 41.7
  Top Layer w0.25: v1(129.473,-22.941) 134.951,-22.941 135.123,-22.769 135.168,-22.814 v1(135.234,-22.814)
  Bottom Layer w0.2: v1(129.473,-22.941) 129.473,-4.634 129.88,-4.226 134.519,-4.226 134.524,-4.23 135.021,-4.23 135.025,-4.226 135.676,-4.226 136.567,-5.118 136.567,-5.84 137.647,-6.92 C43.1@137.647,-7.287 ; v1(135.234,-22.814) R55.2@135.234,-19.267
  Bottom Layer w0.25: C43.1@137.647,-7.287 137.77,-7.41 U15.22@137.77,-11.014
VSYS: R76.2 W3.2 W8.2 W11.1 W13.1 | length 44.7
  Top Layer w0.5: W13.1@141.658,-26.364 141.672,-26.377 146.347,-26.377 165.552,-26.377 W11.1@165.566,-26.364 ; W11.1@165.513,-26.364 W11.1@165.566,-26.364 ; v1(172.924,-26.323) 172.884,-26.364 171.737,-26.364 W11.1@165.566,-26.364
  Bottom Layer w0.5: W8.2@145.598,-17.669 145.598,-21.032 146.281,-21.715 146.281,-26.255 v1(146.347,-26.321) ; W3.2@171.515,-22.489 172.924,-23.899 v1(172.924,-26.323)
  other v1: 167.499,-26.475 157.254,-26.395
VSYS1: D6.1 D7.1 LED1.1 R40.1 W3.1 | length 36.4
  Bottom Layer w0.25: D7.1@152.36,-25.669 160.599,-25.669 162.255,-24.013 168.691,-24.013 W3.1@170.215,-22.489 169.319,-21.594 167.894,-20.169 R40.1@167.894,-19.939 ; LED1.1@169.379,-17.018 169.329,-17.018 167.894,-18.453 R40.1@167.894,-19.939 ; D6.1@176.692,-17.018 D6.1@176.774,-17.101 174.923,-18.952 170.404,-18.952 169.417,-19.939 R40.1@167.894,-19.939
VSYS2: D8.1 D9.1 LED6.1 R51.1 W8.1 | length 23.3
  Bottom Layer w0.2: R51.1@142.159,-17.653 142.159,-16.492 LED6.1@143.323,-15.327
  Bottom Layer w0.5: R51.1@142.159,-17.653 142.175,-17.669 W8.1@144.298,-17.669 144.5,-17.872 144.448,-17.924 144.448,-25.762 D9.1@144.217,-25.993 ; LED6.1@143.323,-15.327 145.855,-12.796 D8.1@152.116,-12.796
pads on no net: C5.2 IC1.4 IC1.5 IC1.6 IC1.7 JP1.1 JP1.8 JP1.9 JP1.10 JP3.4 JP3.5 JP6.4 JP6.5 JP7.3 JP7.4 JP9.4 JP9.5 P1.2 P1.3 Q7.1 Q7.2 Q7.6 SW2.7 SW2.8 U1.9 U1.10 U1.11 U1.12 U1.19 U1.22 U1.23 U1.24 U1.25 U1.26 U2.2 U3.2 U3.3 U3.4 U3.12 U6.1 U6.2 U6.3 U6.4 U6.5 U6.6 U6.13 U6.14 U6.15 U8.5 U8.6 U8.7 U10.1 U10.5 U10.8 U11.1 U11.5 U11.8 U15.2 U15.3 U15.4 U15.12 U16.13 U17.13

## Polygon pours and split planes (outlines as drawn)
no net on Mechanical 13 (solid): 210.185,-4.826
NetC47_1 on Top Layer "NONET_L01_P000" (solid, shelved, pour order 0): 168.021,-23.368 168.021,-21.463 158.75,-21.463 158.75,-22.606 166.37,-22.606 167.132,-23.368
GND on Bottom Layer "Top-No Net" (solid, remove dead copper, pour order 5): 192.972,0.15 192.972,-30.094 -9.276,-30.094 -9.4,-30.216 -9.4,0.408
GND on Top Layer "Top-No Net" (solid, remove dead copper, pour order 6): 193.028,0.332 193.028,-29.912 -9.22,-29.912 -9.345,-30.034 -9.345,0.59

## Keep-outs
Keep-Out Layer:
  lines w0.254: 95.224,0.339 33.949,0.339 33.949,-0.983 33.31,-1.622 14.713,-1.622 14.086,-0.995 14.086,0.399 -9.13,0.399 -9.13,-29.914 14.011,-29.914 14.011,-28.592 14.651,-27.952 33.247,-27.952 33.875,-28.58 33.875,-29.949 192.799,-29.949 192.799,0.216 113.255,0.216 110.88,-2.159 97.734,-2.159 95.23,0.345

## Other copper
Top Layer:
  region net TX_EN: 126.678,-5.426 124.732,-5.426 124.732,-6.928 126.678,-6.928
  region net NetC47_1: 171.719,-15.431 171.252,-15.431 171.252,-16.458 171.719,-16.458
  region net NetC47_1: 171.657,-14.881 164.125,-14.881 164.125,-16.691 171.657,-16.691
  region net 5V_IN: 175.029,-15.466 174.533,-15.466 174.533,-16.596 175.029,-16.596
  region net 5V_IN: 179.33,-16.017 174.533,-16.017 174.533,-16.596 179.33,-16.596
  region net NetC57_1: 147.728,-16.029 140.546,-16.029 140.546,-17.33 147.728,-17.33
  region net NetC57_1: 147.728,-16.579 147.285,-16.579 147.285,-17.696 147.728,-17.696
  region net 5VS_IN: 154.718,-16.533 150.893,-16.533 150.893,-17.348 154.718,-17.348
  region net 5VS_IN: 151.079,-16.58 150.543,-16.58 150.543,-17.698 151.079,-17.698
  region net NetR17_2: 50.877,-21.124 46.227,-21.124 46.227,-22.148 50.877,-22.148
  region: 136.911,-4.129
  region: 136.911,-4.129
  region: 136.911,-4.129
Bottom Layer:
  region net GND: 162.412,-13.598 161.394,-13.598 161.394,-14.262 162.412,-14.262
  region net GND: 136.382,-11.618 135.373,-11.618 135.373,-12.28 136.382,-12.28
  region net NetC39_2: 165.74,-12.764 165.097,-12.764 165.097,-13.775 165.74,-13.775
  region net NetC39_2: 165.097,-12.764 164.751,-12.764 164.751,-13.315 165.097,-13.315
  region net NetC1_2: 161.932,-14.566 161.303,-14.566 161.303,-15.216 161.932,-15.216
  region net NetC4_2: 162.815,-12.764 162.172,-12.764 162.172,-13.323 162.815,-13.323
  region net NetC45_2: 135.908,-13.64 135.345,-13.64 135.345,-14.211 135.908,-14.211
  region net NetC40_2: 135.9,-12.603 135.377,-12.603 135.377,-13.245 135.9,-13.245
  region net NetC41_2: 139.704,-10.672 139.015,-10.672 139.015,-11.761 139.704,-11.761
  region net NetC41_2: 139.704,-10.672 138.715,-10.672 138.715,-11.298 139.704,-11.298
  region net NetC42_2: 136.869,-10.776 136.239,-10.776 136.239,-11.307 136.869,-11.307

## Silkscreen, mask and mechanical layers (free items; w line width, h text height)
Top Overlay:
  circle w0.254: c184.319,-22.44 r1.127
  circle w0.254: c161.135,-1.519 r1.127
  circle w0.254: c130.294,-25.882 r1.127
  circle w0.254: c116.69,-4.809 r1.127
  circle w0.254: c114.501,-14.09 r1.127
  circle w0.254: c108.451,-27.11 r1.127
  text "-5V" at 116.007,-2.838 h1
  text "Ver. 1.2." at -1.819,-3.004 h1.8
  text "5VS" at 160.34,-4.046 h1
  text "+ BAT -" at 163.546,-4.722 h1.52
  text "+ BAT -" at 174.651,-4.722 h1.52
  text "PH" at -2.088,-6.839 h1.2
  text "PRESIÓN" at 25.072,-12.481 h1.2 r90
  text "CONDUCTIVIDAD" at 8.652,-14.348 h1.2 r90
  text "3V3" at 113.81,-16.846 h1
  text "A  B  VCC  GND" at 183.592,-19.093 h1.2 r90
  text "TURBIDEZ" at 8.574,-23.376 h1.2 r90
  text "5V" at 183.852,-24.702 h1
  text "TEMPERATURA" at 24.98,-25.01 h1.2 r90
  text "-3V" at 107.767,-25.416 h1
  text "RST  RX    TX                   GND" at 74.091,-25.834 h1.2
  text "FTDI" at 91.329,-26.84 h1.52 r90
  text "485" at 100.957,-26.925 h1.52 r90
  text "3V" at 129.851,-28.437 h1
